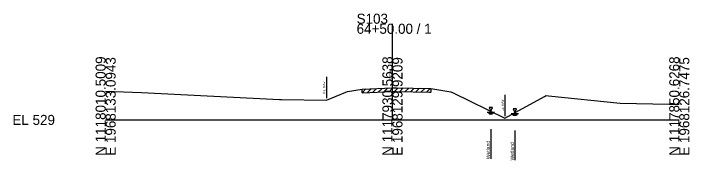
# Model space of a CAD drawing. Extents: x -26 to 163, y -10 to 24018.
# Drawn here: x -25.7 to 162.8, y 12488.7 to 12529.6 of the extents above; entities that cross this region are included whole.
import ezdxf

# ---------------------------------------------------------------- set-up
doc = ezdxf.new("R2010")
doc.units = 0
for name, color, linetype in [('RD_GPK_XS_Cell', 7, 'Continuous'), ('RD_XS_ExGround', 7, 'Continuous'), ('RD_XS_ExPaveRet', 7, 'Continuous'), ('RD_XS_ExRW', 7, 'Continuous'), ('RD_XS_EXWetland', 7, 'Continuous'), ('RD_XS_TX_Elev_EX', 7, 'Continuous')]:
    doc.layers.add(name, color=color, linetype=linetype)

msp = doc.modelspace()

# ---------------------------------------------------------------- linework, layer by layer
at = {"layer": 'RD_GPK_XS_Cell'}
for p, q in [((80, 12500), (80, 12526.8)), ((0, 12500), (80, 12500)), ((80, 12500), (160, 12500))]:
    msp.add_line(p, q, dxfattribs=at)
at = {"layer": 'RD_XS_ExGround'}
msp.add_lwpolyline([(0, 12508.03), (9.99, 12507.67), (48.53, 12505.71), (49.08, 12505.68), (61.56, 12505.53), (67, 12507.76), (67.44, 12507.94), (71.55, 12508.59), (80, 12508.9), (81.11, 12508.93), (90.34, 12508.77), (90.68, 12508.76), (96.27, 12507.85), (96.91, 12507.56), (111.32, 12500.53), (122.39, 12506.54), (122.83, 12506.79), (123.52, 12506.71), (143.52, 12504.7), (157.13, 12504.38), (160, 12504.36)], dxfattribs=at)
at = {"layer": 'RD_XS_ExPaveRet'}
for p, q in [((71.55, 12507.59), (72.59, 12508.63)), ((71.55, 12507.59), (71.55, 12508.59)), ((71.55, 12507.59), (80, 12507.9)), ((73.05, 12507.64), (74.09, 12508.68)), ((74.55, 12507.7), (75.59, 12508.74)), ((76.05, 12507.75), (77.09, 12508.79)), ((77.55, 12507.81), (78.59, 12508.84)), ((79.05, 12507.86), (80.09, 12508.9)), ((80, 12507.9), (81.11, 12507.93)), ((80.55, 12507.91), (81.56, 12508.93)), ((81.11, 12507.93), (90.34, 12507.77)), ((82.05, 12507.92), (83.03, 12508.9)), ((83.55, 12507.89), (84.53, 12508.87)), ((85.05, 12507.86), (86.04, 12508.85)), ((86.55, 12507.84), (87.54, 12508.82)), ((88.05, 12507.81), (89.04, 12508.79)), ((89.55, 12507.78), (90.54, 12508.77)), ((90.34, 12507.77), (90.68, 12507.76)), ((90.68, 12508.76), (90.68, 12507.76))]:
    msp.add_line(p, q, dxfattribs=at)
at = {"layer": 'RD_XS_ExRW'}
for p, q in [((61.56, 12512.03), (61.56, 12506.03)), ((111.32, 12507.03), (111.32, 12501.03))]:
    msp.add_line(p, q, dxfattribs=at)
at = {"layer": 'RD_XS_EXWetland'}
for p, q in [((106.43, 12502.18), (108.43, 12502.18)), ((106.68, 12501.93), (108.18, 12501.93)), ((106.93, 12503.43), (107.43, 12502.43)), ((107.93, 12503.43), (106.93, 12503.43)), ((106.93, 12501.68), (107.93, 12501.68)), ((107.43, 12502.43), (107.93, 12503.43)), ((113.13, 12501.8), (115.13, 12501.8)), ((113.63, 12503.05), (114.13, 12502.05)), ((114.63, 12503.05), (113.63, 12503.05)), ((114.13, 12502.05), (114.63, 12503.05)), ((113.38, 12501.55), (114.88, 12501.55)), ((113.63, 12501.3), (114.63, 12501.3)), ((107.43, 12497.43), (107.43, 12489.18)), ((114.13, 12497.05), (114.13, 12488.8))]:
    msp.add_line(p, q, dxfattribs=at)

# ---------------------------------------------------------------- texts
at = {"layer": 'RD_GPK_XS_Cell'}
for s, p in [('S103', (70, 12526.8)), ('64+50.00 / 1', (70, 12524)), ('EL 529', (-26, 12498.6))]:
    msp.add_text(s, height=2.8, dxfattribs=at).set_placement(p)
for s, p in [('N 1118010.5009', (0, 12490)), ('E 1968133.0943', (2.8, 12490)), ('N 1117930.5638', (80, 12490)), ('E 1968129.9209', (82.8, 12490)), ('N 1117850.6268', (160, 12490)), ('E 1968126.7475', (162.8, 12490))]:
    msp.add_text(s, height=2.8, rotation=90, dxfattribs=at).set_placement(p)
at = {"layer": 'RD_XS_ExRW'}
for p in [(61.31, 12507.37), (111.07, 12502.37)]:
    msp.add_text('Ex. R/W ', height=0.65, rotation=90, dxfattribs=at).set_placement(p)
at = {"layer": 'RD_XS_EXWetland'}
for p in [(107.18, 12489.07), (113.88, 12488.69)]:
    msp.add_text('Wetland ', height=1, rotation=90, dxfattribs=at).set_placement(p)
at = {"layer": 'RD_XS_TX_Elev_EX'}
msp.add_text('537.90', height=0.8, rotation=90, dxfattribs=at).set_placement((79.9, 12510.9))

doc.saveas('drawing.dxf')
